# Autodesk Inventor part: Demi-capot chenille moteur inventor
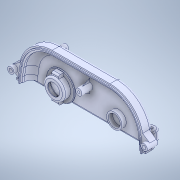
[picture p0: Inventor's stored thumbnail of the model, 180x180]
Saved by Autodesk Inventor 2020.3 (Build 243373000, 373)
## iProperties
Created: 2018-09
Part Number: Demi-capot chenille moteur inventor
Material: Générique
Document SubType Name: Modeling
Designer: ficho
Density: 1 g/cm^3
Appearance: Par défaut
Mass: 15.4725 g
Surface Area: 171.659 cm^2
Volume: 15.4725 cm^3
Sending System: SolidWorks 2015
Last Author: adrien
Last Saved: 2019-01-11
Author: ficho
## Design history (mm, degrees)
feature "Boss.-Extru.18[1]"
feature "Boss.-Extru.18[2]"
feature "Enlèv. mat.-Extru.32[1]"
feature "Enlèv. mat.-Extru.32[2]"
sketch "Esquisse1"
  geometry: C1 r 5.5 at (41.832, 8.1) reference; C2 r 7 at (41.832, 8.1) reference; 1 further point
  dimensions: "d0" = 14 diameter of C2 (derived)
extrude "Extrusion1" cut sketch "Esquisse1" extent not by distance; stored distance "d1" = 11.5; taper "d2" = 0 deg
sketch "Esquisse2"
  geometry: C1 r 5.5 at (-10.168, 8.1) reference; C2 r 5.5 at (42.332, 8.1); C3 r 7 at (42.332, 8.1); 1 further point
  constraints: 2 centre point, 1 coincident
  dimensions: "d3" = 11 diameter of C2; "d4" = 14 diameter of C3; "d5" = 52.5 distance of C1.centre C2.centre
extrude "Extrusion2" join sketch "Esquisse2" distance "d6" = 4; taper "d7" = 0 deg
node "Solide1"
node "Solide2"
node "Solide3"
node "Solide4"
